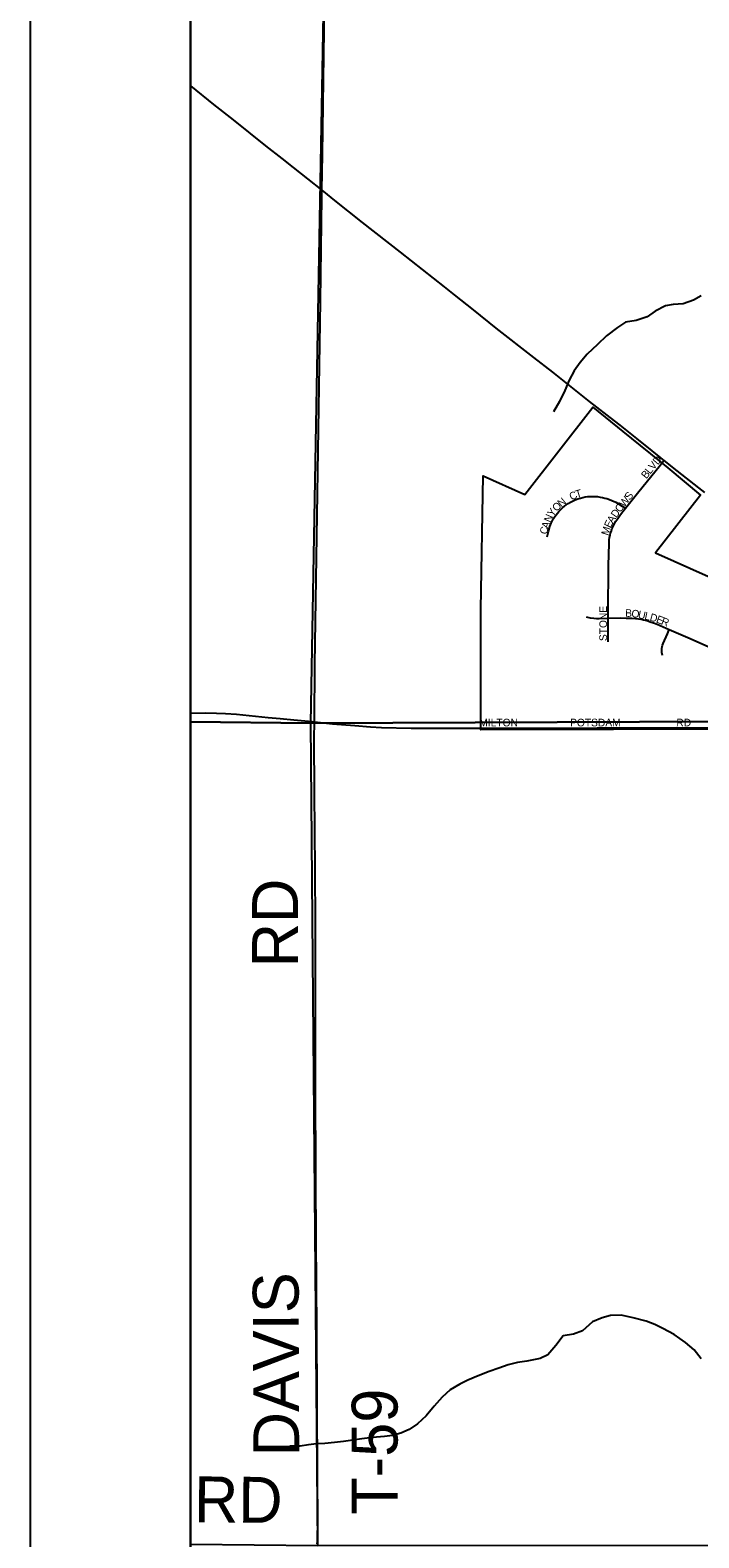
# Model space of a CAD drawing. Extents: x 0 to 680, y 0 to 440.
# Drawn here: x 341.54 to 356.15, y 223.43 to 256.36 of the extents above; entities that cross this region are included whole.
import ezdxf

# ---------------------------------------------------------------- set-up
doc = ezdxf.new("R2010")
doc.units = 0
for name, color, linetype in [('GM_X_Adjacent_County', 7, 'Continuous'), ('GM_X_City_Street', 7, 'Continuous'), ('GM_X_City_Street_Text', 7, 'Continuous'), ('GM_X_Corporation', 7, 'Continuous'), ('GM_X_County', 7, 'Continuous'), ('GM_X_County_Road', 7, 'Continuous'), ('GM_X_County_Road_Text', 7, 'Continuous'), ('GM_X_Minor_River', 7, 'Continuous'), ('GM_X_Section', 7, 'Continuous'), ('GM_X_State_Route', 7, 'Continuous'), ('GM_X_Township', 7, 'Continuous'), ('GM_X_Township_Road', 7, 'Continuous'), ('GM_X_Township_Road_Text', 7, 'Continuous'), ('SH_Data', 7, 'Continuous'), ('SH_Text', 7, 'Continuous')]:
    doc.layers.add(name, color=color, linetype=linetype)

msp = doc.modelspace()

# ---------------------------------------------------------------- linework, layer by layer
at = {"layer": 'GM_X_Adjacent_County'}
msp.add_lwpolyline([(345.039, 415.359), (345.039, 188.757), (345.473, 188.756), (347.217, 188.747), (347.794, 188.745), (350.054, 188.756), (350.975, 188.76), (352.892, 188.767), (353.65, 188.774), (356.075, 188.765), (356.617, 188.773), (363.409, 188.772), (363.555, 188.769), (365.255, 188.724), (373.709, 188.721), (379.321, 188.719), (384.35, 188.722), (392.938, 188.728), (395.267, 188.729), (408.033, 188.58)], dxfattribs=at)
at = {"layer": 'GM_X_City_Street'}
for points in [[(354.543, 245.916), (354.839, 246.282), (355.278, 246.828), (355.383, 246.959)], [(352.835, 245.294), (352.86, 245.406), (352.891, 245.52), (352.918, 245.589), (352.948, 245.65), (352.973, 245.694), (352.999, 245.733), (353.027, 245.771), (353.057, 245.808), (353.091, 245.849), (353.129, 245.888), (353.166, 245.923), (353.209, 245.96), (353.246, 245.99), (353.292, 246.019), (353.345, 246.049), (353.398, 246.077), (353.447, 246.099), (353.502, 246.12), (353.561, 246.138), (353.61, 246.149), (353.666, 246.163), (353.719, 246.17), (353.772, 246.174), (353.824, 246.176), (353.876, 246.176), (353.932, 246.17), (353.993, 246.161), (354.043, 246.152), (354.092, 246.14), (354.134, 246.127), (354.194, 246.106), (354.248, 246.086), (354.333, 246.046), (354.471, 245.96), (354.543, 245.916)], [(354.169, 243.516), (354.169, 243.631), (354.175, 244.666), (354.185, 245.148), (354.188, 245.227), (354.194, 245.276), (354.207, 245.33), (354.219, 245.373), (354.235, 245.425), (354.254, 245.478), (354.28, 245.534), (354.305, 245.584), (354.336, 245.634), (354.375, 245.691), (354.433, 245.778), (354.488, 245.849), (354.543, 245.916)], [(353.686, 243.544), (353.77, 243.527), (353.852, 243.517), (353.914, 243.512), (353.971, 243.512), (354.169, 243.516)], [(354.165, 242.999), (354.169, 243.516)], [(354.169, 243.516), (354.43, 243.521), (354.558, 243.519), (354.683, 243.514), (354.763, 243.508), (354.826, 243.5), (354.883, 243.491), (354.935, 243.48), (355.01, 243.462), (355.084, 243.439), (355.159, 243.413), (355.239, 243.382), (355.499, 243.269)], [(355.35, 242.704), (355.341, 242.767), (355.337, 242.821), (355.337, 242.84), (355.339, 242.859), (355.344, 242.89), (355.354, 242.926), (355.367, 242.963), (355.459, 243.177), (355.499, 243.269)], [(355.499, 243.269), (355.903, 243.094), (356.745, 242.725), (356.825, 242.687), (356.893, 242.652), (356.943, 242.623), (356.978, 242.598), (357.021, 242.565), (357.055, 242.533), (357.098, 242.496), (357.139, 242.449), (357.254, 242.292), (357.389, 242.108)], [(351.305, 241.111), (352.242, 241.114), (352.767, 241.117), (353.927, 241.124), (354.704, 241.121), (355.656, 241.125), (356.64, 241.122), (356.759, 241.126), (356.869, 241.133), (356.995, 241.152), (357.06, 241.164), (357.13, 241.181), (357.176, 241.195)]]:
    msp.add_lwpolyline(points, dxfattribs=at)
at = {"layer": 'GM_X_Corporation'}
msp.add_lwpolyline([(357.179, 241.092), (351.386, 241.077), (351.386, 243.716), (351.437, 246.622), (352.342, 246.219), (353.832, 248.125), (354.486, 247.596), (355.468, 246.801), (356.182, 246.203), (355.196, 244.941), (357.92, 243.729)], dxfattribs=at)
at = {"layer": 'GM_X_County'}
msp.add_lwpolyline([(345.039, 415.359), (345.039, 188.757), (345.473, 188.756), (347.217, 188.747), (347.794, 188.745), (350.054, 188.756), (350.975, 188.76), (352.892, 188.767), (353.65, 188.774), (356.075, 188.765), (356.617, 188.773), (363.409, 188.772), (363.555, 188.769), (365.255, 188.724), (373.709, 188.721), (379.321, 188.719), (384.35, 188.722), (392.938, 188.728), (395.267, 188.729), (408.033, 188.58)], dxfattribs=at)
at = {"layer": 'GM_X_County_Road'}
for points in [[(345.039, 241.442), (345.378, 241.447), (345.61, 241.441), (345.807, 241.432), (346.047, 241.418), (346.74, 241.348), (347.001, 241.322), (347.296, 241.293), (347.701, 241.259), (347.747, 241.255)], [(347.747, 241.255), (348.143, 241.211), (348.634, 241.171), (348.973, 241.141), (349.213, 241.13), (349.86, 241.113), (350.375, 241.113), (351.305, 241.111)]]:
    msp.add_lwpolyline(points, dxfattribs=at)
at = {"layer": 'GM_X_Minor_River'}
for points in [[(356.2, 250.555), (356.03, 250.458), (355.806, 250.383), (355.584, 250.368), (355.416, 250.339), (355.192, 250.217), (355.021, 250.1), (354.777, 250.018), (354.541, 249.977), (354.371, 249.867), (354.132, 249.685), (353.932, 249.495), (353.706, 249.279), (353.554, 249.102), (353.422, 248.917), (353.316, 248.712), (353.217, 248.486), (353.103, 248.247), (352.971, 248.022)], [(356.196, 227.338), (356.047, 227.536), (355.856, 227.701), (355.606, 227.875), (355.36, 228.002), (355.182, 228.093), (354.995, 228.165), (354.709, 228.239), (354.448, 228.292), (354.22, 228.291), (354.031, 228.235), (353.821, 228.153), (353.608, 227.95), (353.405, 227.881), (353.182, 227.846), (353.023, 227.635), (352.85, 227.431), (352.68, 227.347), (352.39, 227.294), (352.182, 227.265), (351.979, 227.21), (351.776, 227.141), (351.566, 227.065), (351.329, 226.97), (351.098, 226.875), (350.922, 226.785), (350.711, 226.662), (350.539, 226.505), (350.366, 226.308), (350.187, 226.098), (350.001, 225.921), (349.817, 225.798), (349.64, 225.715), (349.451, 225.665), (349.276, 225.643), (349.021, 225.622), (348.785, 225.594), (348.59, 225.565), (348.381, 225.536), (348.186, 225.514), (347.977, 225.492), (347.796, 225.483), (347.621, 225.467), (347.439, 225.438), (347.211, 225.436)]]:
    msp.add_lwpolyline(points, dxfattribs=at)
at = {"layer": 'GM_X_Section'}
for points in [[(345.039, 259.579), (345.039, 241.25), (347.667, 241.224), (347.996, 259.569)], [(347.996, 259.569), (365.663, 259.44), (365.612, 241.297), (347.667, 241.224)], [(345.039, 241.25), (345.039, 223.295), (347.826, 223.264), (347.667, 241.224)], [(347.667, 241.224), (365.612, 241.297), (365.656, 223.253), (347.826, 223.264)]]:
    msp.add_lwpolyline(points, close=True, dxfattribs=at)
at = {"layer": 'GM_X_State_Route'}
for points in [[(345.039, 255.139), (345.544, 254.737), (345.972, 254.396), (346.682, 253.828), (347.037, 253.553), (347.286, 253.357), (347.914, 252.86), (347.949, 252.831), (348.185, 252.64), (348.794, 252.158), (349.62, 251.507), (350.584, 250.75), (350.798, 250.58), (351.219, 250.247), (351.715, 249.851), (352.533, 249.209), (352.947, 248.886), (353.462, 248.478), (353.751, 248.25)], [(353.751, 248.25), (354.296, 247.828), (354.419, 247.731)], [(354.419, 247.731), (354.785, 247.439), (355.123, 247.167), (355.311, 247.015), (355.383, 246.959), (355.665, 246.737), (356.141, 246.363)], [(356.141, 246.363), (356.27, 246.257)]]:
    msp.add_lwpolyline(points, dxfattribs=at)
at = {"layer": 'GM_X_Township'}
msp.add_lwpolyline([(345.039, 295.02), (345.039, 188.757), (345.473, 188.756), (347.217, 188.747), (347.794, 188.745), (350.054, 188.756), (350.975, 188.76), (352.892, 188.767), (353.65, 188.774), (356.075, 188.765), (356.617, 188.773), (363.409, 188.772), (363.555, 188.769), (365.255, 188.724), (373.709, 188.721), (379.321, 188.719), (384.35, 188.722), (392.938, 188.728), (395.267, 188.729), (408.033, 188.58), (418.103, 188.464), (418.29, 277.524)], dxfattribs=at)
at = {"layer": 'GM_X_Township_Road'}
for points in [[(347.914, 252.86), (347.926, 253.644), (348.007, 259.616)], [(347.747, 241.255), (347.756, 242.505), (347.881, 250.442), (347.912, 252.72), (347.914, 252.86)], [(347.773, 235.537), (347.771, 236.846), (347.763, 238.029), (347.752, 239.714), (347.745, 240.886), (347.747, 241.255)], [(347.81, 223.299), (347.816, 223.353), (347.819, 223.396), (347.82, 223.797), (347.814, 224.771), (347.799, 228.065), (347.793, 228.885), (347.777, 231.186), (347.773, 233.485), (347.772, 233.802), (347.773, 235.455), (347.773, 235.537)]]:
    msp.add_lwpolyline(points, dxfattribs=at)
at = {"layer": 'SH_Data'}
for p, q in [((341.539, 418.859), (341.539, 173.859)), ((345.039, 415.359), (345.039, 177.359))]:
    msp.add_line(p, q, dxfattribs=at)
at = {"layer": 'SH_Text'}
for points in [[(345.039, 415.359), (583.039, 415.359), (583.039, 177.359), (345.039, 177.359)], [(345.039, 415.359), (345.039, 177.359), (583.038, 177.359), (583.038, 415.359)]]:
    msp.add_lwpolyline(points, close=True, dxfattribs=at)

# ---------------------------------------------------------------- texts
at = {"layer": 'GM_X_City_Street_Text'}
for s, height, rotation, p in [('V', 0.167, 50.6898, (355.156, 246.74)), ('D', 0.167, 49.215, (355.248, 246.852)), ('B', 0.167, 50.978, (354.999, 246.546)), ('L', 0.167, 50.9711, (355.082, 246.649)), ('C', 0.167, 24.6259, (353.363, 246.084)), ('T', 0.167, 16.6247, (353.477, 246.137)), ('O', 0.167, 45.1004, (353.04, 245.832)), ('N', 0.167, 39.2402, (353.141, 245.933)), ('O', 0.167, 52.5793, (354.428, 245.812)), ('W', 0.167, 51.4688, (354.517, 245.928)), ('S', 0.167, 51.3487, (354.636, 246.078)), ('N', 0.167, 66.8875, (352.904, 245.593)), ('Y', 0.167, 53.1257, (352.956, 245.719)), ('E', 0.167, 63.5327, (354.216, 245.471)), ('A', 0.167, 57.5892, (354.266, 245.572)), ('D', 0.167, 54.503, (354.344, 245.694)), ('C', 0.167, 72.1027, (352.819, 245.331)), ('A', 0.167, 72.0904, (352.86, 245.457)), ('M', 0.167, 72.9589, (354.167, 245.309)), ('STONE', 0.1669, 90, (354.14, 243.016)), ('B', 0.167, 358.4213, (354.537, 243.547)), ('O', 0.167, 350.8683, (354.664, 243.544)), ('U', 0.167, 347.6419, (354.806, 243.521)), ('L', 0.167, 347.5245, (354.949, 243.49)), ('D', 0.167, 344.718, (355.062, 243.465)), ('E', 0.167, 339.452, (355.2, 243.427)), ('R', 0.167, 338.6225, (355.309, 243.386)), ('MILTON', 0.1669, 0, (351.351, 241.153)), ('POTSDAM', 0.1669, 0, (353.334, 241.153)), ('RD', 0.1669, 0, (355.655, 241.153))]:
    msp.add_text(s, height=height, rotation=rotation, dxfattribs=at).set_placement(p)
at = {"layer": 'GM_X_County_Road_Text'}
msp.add_text('RD', height=1.0014, rotation=359.5042, dxfattribs=at).set_placement((345.115, 223.774))
at = {"layer": 'GM_X_Township_Road_Text'}
for s, rotation, p in [('RD', 90, (347.389, 235.893)), ('DAVIS', 90.2248, (347.418, 225.214)), ('T-59', 90, (349.565, 223.938))]:
    msp.add_text(s, height=1.0014, rotation=rotation, dxfattribs=at).set_placement(p)

doc.saveas('drawing.dxf')
